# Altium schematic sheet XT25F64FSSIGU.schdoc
size 127 x 101 mm
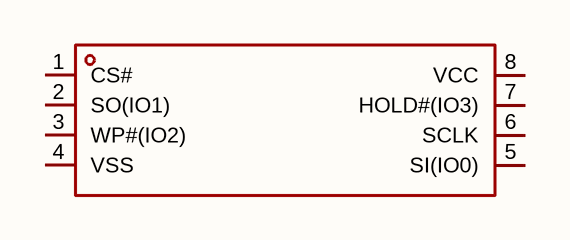
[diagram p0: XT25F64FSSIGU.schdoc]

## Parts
U?  xt25f64fssigu  [SOP-8_L5.3-W5.2-P1.27-LS7.9-BL]  (value not drawn)

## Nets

Not connected (* = marked no-connect by the designer): U? 1(CS#) 2(SO(IO1)) 3(WP#(IO2)) 4(VSS) 5(SI(IO0)) 6(SCLK) 7(HOLD#(IO3)) 8(VCC)

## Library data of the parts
U? = xt25f64fssigu: 接口类型:SPI;存储容量:64Mbit;时钟频率(fc):133MHz;; Manufacturer: XTX(芯天下); AddInBom: yes; ModelId: b3bace262c53465a9e6115a2e0c7b3cc; ModelTransform: 205.905,311.023,0,0,0,0,0,0,0; Interface: SPI; Memory Size: 64Mbit; Clock Frequency: 133MHz; Voltage - Supply: 2.7V~3.6V; Standby Supply Current: 0.3uA; Program / Erase Cycles: 100000次; Page Programming Time (Tpp): 400us; Data Retention - TDR (Year): 20年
